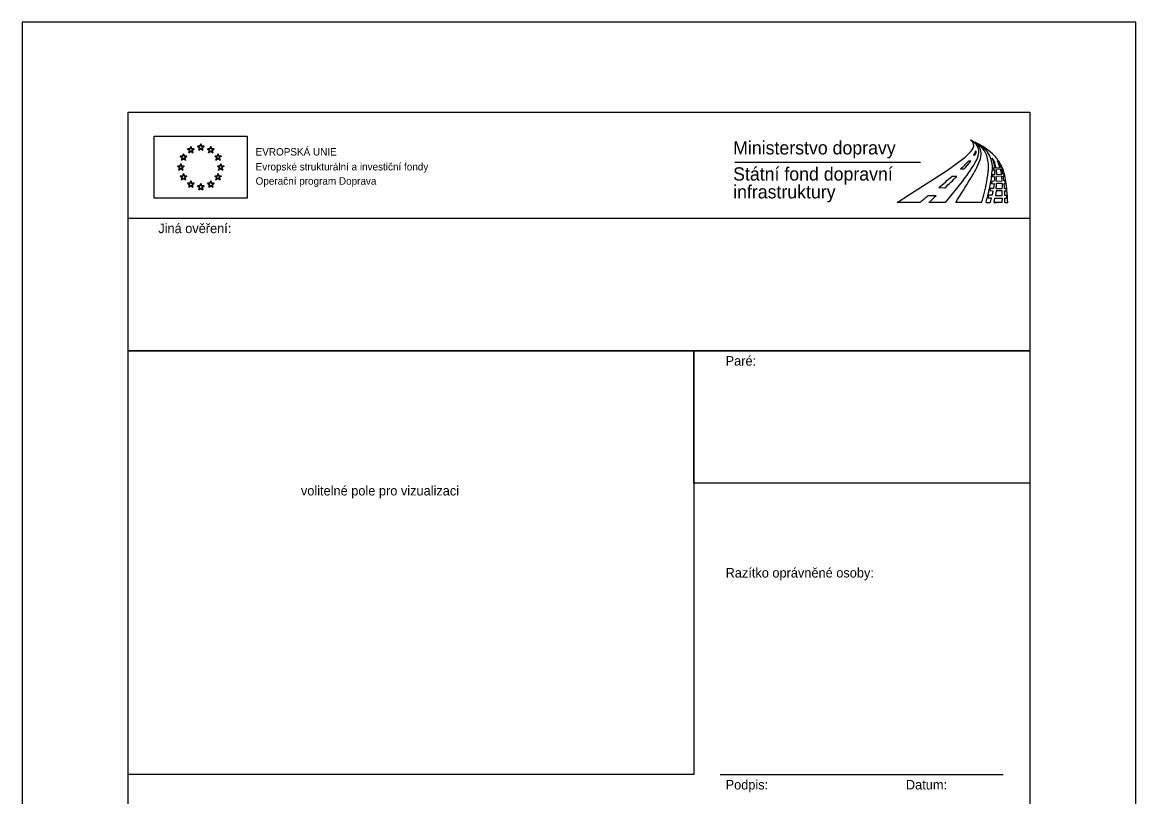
# Model space of a CAD drawing. Extents: x -172 to -151, y 333 to 362.7.
# Drawn here: x -172 to -151, y 348.08 to 362.7 of the extents above; entities that cross this region are included whole.
import ezdxf

# ---------------------------------------------------------------- set-up
doc = ezdxf.new("R2010")
doc.units = 0
for name, color, linetype in [('Default', 7, 'Continuous'), ('Rozpiska_Logo', 7, 'Continuous'), ('Rozpiska_pola_3', 7, 'Continuous'), ('Rozpiska_pole_1', 7, 'Continuous'), ('Rozpiska_pole_2', 7, 'Continuous')]:
    doc.layers.add(name, color=color, linetype=linetype)

msp = doc.modelspace()

# ---------------------------------------------------------------- linework, layer by layer
at = {"layer": 'Default'}
for p, q in [((-151, 362.7), (-172, 362.7)), ((-172, 362.7), (-172, 333)), ((-151, 333), (-151, 362.7))]:
    msp.add_line(p, q, dxfattribs=at)
msp.add_lwpolyline([(-172, 333), (-151, 333), (-151, 362.7), (-172, 362.7)], close=True, dxfattribs=at)
at = {"layer": 'Rozpiska_Logo'}
msp.add_line((-158.558, 360.062), (-155.061, 360.062), dxfattribs=at)
for points in [[(-169.51, 360.549), (-167.757, 360.549), (-167.756, 359.38), (-169.51, 359.38), (-169.51, 360.549)], [(-168.696, 360.36), (-168.648, 360.36), (-168.633, 360.406), (-168.618, 360.36), (-168.57, 360.36), (-168.609, 360.332), (-168.594, 360.286), (-168.633, 360.315), (-168.672, 360.286), (-168.657, 360.332), (-168.696, 360.36)], [(-168.657, 360.332), (-168.672, 360.286), (-168.633, 360.315), (-168.594, 360.286), (-168.609, 360.332), (-168.57, 360.36), (-168.618, 360.36), (-168.633, 360.406), (-168.648, 360.36), (-168.696, 360.36), (-168.657, 360.332)], [(-169.021, 360.173), (-168.973, 360.173), (-168.958, 360.219), (-168.943, 360.173), (-168.895, 360.173), (-168.934, 360.144), (-168.919, 360.099), (-168.958, 360.127), (-168.997, 360.099), (-168.982, 360.144), (-169.021, 360.173)], [(-168.982, 360.144), (-168.997, 360.099), (-168.958, 360.127), (-168.919, 360.099), (-168.934, 360.144), (-168.895, 360.173), (-168.943, 360.173), (-168.958, 360.219), (-168.973, 360.173), (-169.021, 360.173), (-168.982, 360.144)], [(-168.884, 360.31), (-168.836, 360.31), (-168.821, 360.356), (-168.806, 360.31), (-168.758, 360.31), (-168.797, 360.282), (-168.782, 360.236), (-168.821, 360.264), (-168.86, 360.236), (-168.845, 360.282), (-168.884, 360.31)], [(-168.845, 360.282), (-168.86, 360.236), (-168.821, 360.264), (-168.782, 360.236), (-168.797, 360.282), (-168.758, 360.31), (-168.806, 360.31), (-168.821, 360.356), (-168.836, 360.31), (-168.884, 360.31), (-168.845, 360.282)], [(-168.509, 360.31), (-168.46, 360.31), (-168.446, 360.356), (-168.431, 360.31), (-168.382, 360.31), (-168.421, 360.282), (-168.407, 360.236), (-168.446, 360.264), (-168.485, 360.236), (-168.47, 360.282), (-168.509, 360.31)], [(-168.47, 360.282), (-168.485, 360.236), (-168.446, 360.264), (-168.407, 360.236), (-168.421, 360.282), (-168.382, 360.31), (-168.431, 360.31), (-168.446, 360.356), (-168.46, 360.31), (-168.509, 360.31), (-168.47, 360.282)], [(-168.371, 360.173), (-168.323, 360.173), (-168.308, 360.219), (-168.293, 360.173), (-168.245, 360.173), (-168.284, 360.145), (-168.269, 360.099), (-168.308, 360.127), (-168.347, 360.099), (-168.332, 360.145), (-168.371, 360.173)], [(-168.332, 360.145), (-168.347, 360.099), (-168.308, 360.127), (-168.269, 360.099), (-168.284, 360.145), (-168.245, 360.173), (-168.293, 360.173), (-168.308, 360.219), (-168.323, 360.173), (-168.371, 360.173), (-168.332, 360.145)], [(-154.058, 360.189), (-154.038, 360.189)], [(-154.007, 360.264), (-154.007, 360.264), (-154.023, 360.264)], [(-169.072, 359.985), (-169.023, 359.985), (-169.008, 360.031), (-168.994, 359.985), (-168.945, 359.985), (-168.984, 359.957), (-168.969, 359.911), (-169.008, 359.939), (-169.047, 359.911), (-169.033, 359.957), (-169.072, 359.985)], [(-169.033, 359.957), (-169.047, 359.911), (-169.008, 359.939), (-168.969, 359.911), (-168.984, 359.957), (-168.945, 359.985), (-168.994, 359.985), (-169.008, 360.031), (-169.023, 359.985), (-169.072, 359.985), (-169.033, 359.957)], [(-168.321, 359.985), (-168.273, 359.985), (-168.258, 360.031), (-168.243, 359.985), (-168.195, 359.985), (-168.234, 359.957), (-168.219, 359.911), (-168.258, 359.939), (-168.297, 359.911), (-168.282, 359.957), (-168.321, 359.985)], [(-168.282, 359.957), (-168.297, 359.911), (-168.258, 359.939), (-168.219, 359.911), (-168.234, 359.957), (-168.195, 359.985), (-168.243, 359.985), (-168.258, 360.031), (-168.273, 359.985), (-168.321, 359.985), (-168.282, 359.957)], [(-155.069, 359.3), (-155.499, 359.3), (-155.268, 359.451), (-154.548, 359.91), (-154.268, 360.115)], [(-154.108, 360.077), (-154.108, 360.077), (-154.153, 360.078)], [(-153.658, 359.947), (-153.691, 359.945), (-153.692, 359.914), (-153.659, 359.917)], [(-153.556, 359.953), (-153.636, 359.948)], [(-153.529, 359.928), (-153.516, 359.928), (-153.526, 359.955), (-153.541, 359.954)], [(-169.021, 359.797), (-168.973, 359.797), (-168.958, 359.843), (-168.943, 359.797), (-168.895, 359.797), (-168.934, 359.769), (-168.919, 359.723), (-168.958, 359.752), (-168.997, 359.723), (-168.982, 359.769), (-169.021, 359.797)], [(-168.982, 359.769), (-168.997, 359.723), (-168.958, 359.752), (-168.919, 359.723), (-168.934, 359.769), (-168.895, 359.797), (-168.943, 359.797), (-168.958, 359.843), (-168.973, 359.797), (-169.021, 359.797), (-168.982, 359.769)], [(-168.371, 359.798), (-168.323, 359.798), (-168.308, 359.843), (-168.293, 359.798), (-168.245, 359.798), (-168.284, 359.769), (-168.269, 359.723), (-168.308, 359.752), (-168.347, 359.723), (-168.332, 359.769), (-168.371, 359.798)], [(-168.332, 359.769), (-168.347, 359.723), (-168.308, 359.752), (-168.269, 359.723), (-168.284, 359.769), (-168.245, 359.798), (-168.293, 359.798), (-168.308, 359.843), (-168.323, 359.798), (-168.371, 359.798), (-168.332, 359.769)], [(-154.376, 359.791), (-154.376, 359.791), (-154.469, 359.791)], [(-154.302, 359.932), (-154.236, 359.932)], [(-153.659, 359.823), (-153.699, 359.82), (-153.704, 359.785), (-153.661, 359.787)], [(-153.548, 359.926), (-153.629, 359.919)], [(-153.526, 359.793), (-153.624, 359.789)], [(-153.621, 359.825), (-153.53, 359.83)], [(-153.5, 359.794), (-153.482, 359.795), (-153.49, 359.832), (-153.507, 359.831)], [(-168.884, 359.66), (-168.836, 359.66), (-168.821, 359.706), (-168.806, 359.66), (-168.758, 359.66), (-168.797, 359.632), (-168.782, 359.586), (-168.821, 359.614), (-168.86, 359.586), (-168.845, 359.632), (-168.884, 359.66)], [(-168.845, 359.632), (-168.86, 359.586), (-168.821, 359.614), (-168.782, 359.586), (-168.797, 359.632), (-168.758, 359.66), (-168.806, 359.66), (-168.821, 359.706), (-168.836, 359.66), (-168.884, 359.66), (-168.845, 359.632)], [(-168.696, 359.61), (-168.648, 359.61), (-168.633, 359.656), (-168.618, 359.61), (-168.57, 359.61), (-168.609, 359.582), (-168.594, 359.536), (-168.633, 359.564), (-168.672, 359.536), (-168.657, 359.582), (-168.696, 359.61)], [(-168.657, 359.582), (-168.672, 359.536), (-168.633, 359.564), (-168.594, 359.536), (-168.609, 359.582), (-168.57, 359.61), (-168.618, 359.61), (-168.633, 359.656), (-168.648, 359.61), (-168.696, 359.61), (-168.657, 359.582)], [(-168.509, 359.66), (-168.46, 359.66), (-168.445, 359.706), (-168.431, 359.66), (-168.382, 359.66), (-168.421, 359.632), (-168.406, 359.586), (-168.445, 359.614), (-168.484, 359.586), (-168.47, 359.632), (-168.509, 359.66)], [(-168.47, 359.632), (-168.484, 359.586), (-168.445, 359.614), (-168.406, 359.586), (-168.421, 359.632), (-168.382, 359.66), (-168.431, 359.66), (-168.445, 359.706), (-168.46, 359.66), (-168.509, 359.66), (-168.47, 359.632)], [(-154.251, 359.724), (-154.592, 359.3), (-154.899, 359.3)], [(-154.714, 359.582), (-154.6, 359.576)], [(-153.667, 359.698), (-153.717, 359.696), (-153.723, 359.653), (-153.672, 359.654), (-153.684, 359.563), (-153.739, 359.563), (-153.75, 359.522), (-153.692, 359.521), (-153.71, 359.435), (-153.775, 359.436), (-153.782, 359.389), (-153.725, 359.388), (-153.745, 359.3)], [(-153.631, 359.563), (-153.516, 359.563)], [(-153.516, 359.656), (-153.628, 359.654)], [(-153.625, 359.7), (-153.521, 359.704)], [(-153.482, 359.657), (-153.457, 359.657), (-153.464, 359.706), (-153.489, 359.705)], [(-153.473, 359.518), (-153.44, 359.518), (-153.446, 359.563), (-153.476, 359.563)], [(-154.765, 359.421), (-154.765, 359.421), (-154.912, 359.426)], [(-153.635, 359.517), (-153.645, 359.433), (-153.52, 359.43), (-153.518, 359.516), (-153.635, 359.517)], [(-153.468, 359.3), (-153.469, 359.381), (-153.429, 359.38), (-153.434, 359.428), (-153.47, 359.429)], [(-153.907, 359.3), (-154.395, 359.3)], [(-153.823, 359.3), (-153.745, 359.3)], [(-153.673, 359.3), (-153.627, 359.3)], [(-153.468, 359.3), (-153.412, 359.3)]]:
    msp.add_lwpolyline(points, dxfattribs=at)
msp.add_lwpolyline([(-153.673, 359.3), (-153.656, 359.383), (-153.522, 359.383), (-153.525, 359.299)], close=True, dxfattribs=at)
for centre, radius, start, end in [((-154.171, 360.372), 0.116, 333.7821, 60.3253), ((-154.236, 360.211), 0.289, 35.1291, 64.7751), ((-154.341, 359.916), 0.605, 44.354, 59.6129), ((-154.21, 360.194), 0.299, 8.8325, 54.3171), ((-154.182, 360.249), 0.223, 358.3059, 35.1291), ((-163.824, 347.625), 16.135, 51.8348, 52.3632), ((-154.426, 359.492), 1.018, 55.8173, 63.4675), ((-154.727, 360.767), 0.797, 305.1305, 325.9532), ((-154.177, 360.291), 0.156, 319.6022, 350.325), ((-154.171, 360.288), 0.166, 323.7342, 351.8118), ((-154.271, 360.252), 0.312, 331.1155, 358.3059), ((-154.373, 360.248), 0.459, 339.6691, 359.0927), ((-154.227, 360.031), 0.443, 21.6804, 44.0388), ((-154.292, 359.609), 0.847, 45.7577, 58.8317), ((-154.148, 359.984), 0.44, 29.5083, 48.0349), ((-154.372, 359.982), 0.596, 354.8309, 20.9259), ((-154.14, 359.984), 0.433, 12.5999, 30.087), ((-154.288, 359.601), 0.85, 32.4145, 46.3283), ((-155.972, 361.792), 2.499, 311.9225, 316.7053), ((-156.307, 361.376), 2.637, 321.2414, 331.1155), ((-157.757, 363.183), 4.793, 317.2846, 319.5966), ((-155.441, 360.644), 1.598, 326.3997, 339.6645), ((-154.172, 359.959), 0.47, 350.7277, 14.6627), ((-154.073, 359.894), 0.441, 6.9884, 33.3949), ((-154.229, 359.908), 0.572, 3.8889, 23.6112), ((-154.051, 359.777), 0.539, 19.1508, 35.05), ((-154.708, 359.574), 1.213, 18.2045, 25.0006), ((-154.099, 359.703), 0.636, 13.4543, 33.7828), ((-159.762, 365.729), 7.955, 309.3914, 311.7102), ((-158.427, 363.773), 5.68, 312.3671, 315.4937), ((-194.272, 384.384), 47.111, 327.8282, 328.4861), ((-155.451, 360.036), 1.676, 348.0644, 356.2998), ((-155.742, 360.044), 2.04, 348.131, 355.4957), ((-151.798, 359.621), 1.871, 174.904, 177.6286), ((-154.822, 359.867), 1.164, 357.822, 2.4688), ((-154.578, 359.793), 0.957, 1.9262, 7.6145), ((-158.852, 359.8), 5.228, 358.9091, 359.8809), ((-154.338, 359.727), 0.815, 7.2316, 14.102), ((-154.11, 359.743), 0.61, 8.3249, 17.6578), ((-155.463, 359.637), 1.943, 1.988, 4.6084), ((-153.878, 359.705), 0.388, 0.0904, 13.2769), ((-155.054, 359.446), 1.625, 2.7985, 14.4251), ((-156.615, 360.174), 2.846, 342.1151, 350.2059), ((-156.968, 360.229), 3.279, 343.5415, 349.3721), ((-154.169, 359.63), 0.541, 352.9784, 2.6252), ((-154.147, 359.614), 0.633, 355.4573, 3.8566), ((-154.546, 359.538), 1.071, 1.3852, 6.3824), ((-156.71, 359.142), 3.301, 2.7322, 6.6695), ((-152.893, 356.762), 3.342, 127.1682, 130.6153), ((-153.049, 357.406), 2.647, 130.4231, 134.3309), ((-157.411, 359.348), 3.942, 1.1818, 2.4809)]:
    msp.add_arc(centre, radius, start, end, dxfattribs=at)
at = {"layer": 'Rozpiska_pola_3'}
msp.add_line((-158.835, 348.5), (-153.5, 348.5), dxfattribs=at)
at = {"layer": 'Rozpiska_pole_1'}
msp.add_lwpolyline([(-170, 361), (-153, 361), (-153, 334.5), (-170, 334.5)], close=True, dxfattribs=at)
at = {"layer": 'Rozpiska_pole_2'}
for points in [[(-170, 359), (-153, 359), (-153, 356.5), (-170, 356.5)], [(-170, 356.5), (-159.335, 356.5), (-159.335, 348.5), (-170, 348.5)], [(-159.335, 356.5), (-153, 356.5), (-153, 354), (-159.335, 354)]]:
    msp.add_lwpolyline(points, close=True, dxfattribs=at)

# ---------------------------------------------------------------- texts
at = {"layer": 'Default'}
msp.add_text('volitelné pole pro vizualizaci', height=0.17997, dxfattribs=at).set_placement((-166.745, 353.769))
at = {"layer": 'Rozpiska_Logo'}
for s, height, p in [('EVROPSKÁ UNIE', 0.14, (-167.599, 360.185)), ('Ministerstvo dopravy', 0.25, (-158.593, 360.205)), ('Evropské strukturální a investiční fondy', 0.14, (-167.599, 359.903)), ('Státní fond dopravní', 0.25, (-158.593, 359.712)), ('Operační program Doprava', 0.14, (-167.599, 359.634)), ('infrastruktury', 0.25, (-158.593, 359.375))]:
    msp.add_text(s, height=height, rotation=0.0062, dxfattribs=at).set_placement(p)
at = {"layer": 'Rozpiska_pola_3'}
for s, p in [('Paré:', (-158.735, 356.22)), ('Razítko oprávněné osoby:', (-158.735, 352.22)), ('Podpis:', (-158.735, 348.22)), ('Datum:', (-155.335, 348.22))]:
    msp.add_text(s, height=0.18, dxfattribs=at).set_placement(p)
at = {"layer": 'Rozpiska_pole_2'}
msp.add_text('Jiná ověření:', height=0.18, dxfattribs=at).set_placement((-169.435, 358.72))

doc.saveas('drawing.dxf')
